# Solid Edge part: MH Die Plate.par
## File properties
Author: davee
Template: Normal.par
Last saved by: davee
Revision: 61
Application: Solid Edge
Accuracy: 0.990
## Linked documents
Loose Support Solid.par
LTS 300A SHAFT SUPPORT etd.par
LTS 300A SHAFT SUPPORT etd Solid.par
Loose Support.par
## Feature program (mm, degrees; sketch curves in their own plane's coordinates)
sketch for "unnamed Protrusion 1" plane through (0, 0, 0) normal (0, 0, 1) x-axis (1, 0, 0)
  line (-100, -100) -> (100, -100)
  line (100, -100) -> (100, 100)
  line (100, 100) -> (-100, 100)
  line (-100, 100) -> (-100, -100)
  dimension (linear) = 100
  dimension (linear) = 100
extrude "unnamed Protrusion 1" add finite 36.2 along -normal
sketch for "Hole_1" plane through (0, 0, 0) normal (0, 0, 1) x-axis (1, 0, 0)
hole "Hole_1" diameter 6 through
sketch for "Hole_2" plane through (0, 0, -36.2) normal (0, 0, -1) x-axis (-1, 0, 0)
  hole centre (-80, -49) bore radius 5.053
hole "Hole_2" finite  VBottomAngle = 118 deg; ThreadDepth = 2 mm
sketch for "unnamed Hole 1" plane through (0, 0, -36.2) normal (0, 0, -1) x-axis (-1, 0, 0)
  hole centre (80, -49) bore radius 5.053
hole "unnamed Hole 1" finite
sketch for "unnamed Hole 2" plane through (0, 0, -36.2) normal (0, 0, -1) x-axis (-1, 0, 0)
  hole centre (80, 49) bore radius 5.053
hole "unnamed Hole 2" finite
sketch for "unnamed Hole 3" plane through (0, 0, -36.2) normal (0, 0, -1) x-axis (-1, 0, 0)
  hole centre (-80, 49) bore radius 5.053
hole "unnamed Hole 3" finite
pattern "unnamed Pattern 1" of "Hole_2", "unnamed Hole 1", "unnamed Hole 2", "unnamed Hole 3"
sketch for "ExtrudedCutout_1" #1 plane through (0, 0, -36.2) normal (0, 0, -1) x-axis (-1, 0, 0)
  circle centre (77, 77) radius 16
sketch for "ExtrudedCutout_1" #2 plane through (0, 0, -36.2) normal (0, 0, -1) x-axis (-1, 0, 0)
  circle centre (77, -77) radius 16
sketch for "ExtrudedCutout_1" #3 plane through (0, 0, -36.2) normal (0, 0, -1) x-axis (-1, 0, 0)
  circle centre (-77, -77) radius 16
sketch for "ExtrudedCutout_1" #4 plane through (0, 0, -36.2) normal (0, 0, -1) x-axis (-1, 0, 0)
  circle centre (-77, 77) radius 16
extrude "ExtrudedCutout_1" cut finite 6 along -normal
sketch for "unnamed Cutout 1" #1 plane through (0, 0, -36.2) normal (0, 0, -1) x-axis (-1, 0, 0)
  circle centre (77, 77) radius 13.5
sketch for "unnamed Cutout 1" #2 plane through (0, 0, -36.2) normal (0, 0, -1) x-axis (-1, 0, 0)
  circle centre (77, -77) radius 13.5
sketch for "unnamed Cutout 1" #3 plane through (0, 0, -36.2) normal (0, 0, -1) x-axis (-1, 0, 0)
  circle centre (-77, -77) radius 13.5
sketch for "unnamed Cutout 1" #4 plane through (0, 0, -36.2) normal (0, 0, -1) x-axis (-1, 0, 0)
  circle centre (-77, 77) radius 13.5
extrude "unnamed Cutout 1" cut through along -normal
sketch for "Hole_6" plane through (0, 0, -36.2) normal (0, 0, -1) x-axis (-1, 0, 0)
hole "Hole_6" diameter 14 through  CounterBoreDepth = 5 mm; VBottomAngle = 118 deg
boolean "unnamed Boolean 1"
boolean "unnamed Boolean 2"
boolean "unnamed Boolean 3"
boolean "unnamed Boolean 4"
sketch for "Hole_18" plane through (0, 0, 0) normal (0, 0, 1) x-axis (0, -1, 0)
hole "Hole_18" diameter 3 through
sketch for "unnamed Hole 4" plane through (0, 0, 0) normal (0, 0, 1) x-axis (0, -1, 0)
hole "unnamed Hole 4" through
sketch for "unnamed Hole 5" plane through (0, 0, 0) normal (0, 0, 1) x-axis (0, -1, 0)
hole "unnamed Hole 5" through
sketch for "unnamed Hole 6" plane through (0, 0, 0) normal (0, 0, 1) x-axis (0, -1, 0)
  hole centre (-74, 13.1725) bore radius 1.5
  dimension (linear) = 74
hole "unnamed Hole 6" through
sketch for "Hole_23" plane through (0, 0, 0) normal (0, 0, 1) x-axis (1, 0, 0)
hole "Hole_23" diameter 6 through
sketch for "unnamed Hole 7" plane through (0, 0, 0) normal (0, 0, 1) x-axis (1, 0, 0)
hole "unnamed Hole 7" through
sketch for "Hole_25" plane through (0, 0, 0) normal (0, 0, 1) x-axis (1, 0, 0)
  hole centre (40, 85) bore radius 5
hole "Hole_25" diameter 10 through  VBottomAngle = 118 deg
sketch for "unnamed Hole 8" plane through (0, 0, 0) normal (0, 0, 1) x-axis (1, 0, 0)
hole "unnamed Hole 8" through
sketch for "unnamed Hole 9" plane through (0, 0, 0) normal (0, 0, 1) x-axis (1, 0, 0)
hole "unnamed Hole 9" through
sketch for "unnamed Hole 10" plane through (0, 0, 0) normal (0, 0, 1) x-axis (1, 0, 0)
hole "unnamed Hole 10" through
pattern "unnamed Pattern 2" of "Hole_18", "unnamed Hole 4", "unnamed Hole 5", "unnamed Hole 6"
pattern "unnamed Pattern 3" of "Hole_23", "unnamed Hole 7"
pattern "unnamed Pattern 4" of "Hole_25", "unnamed Hole 8", "unnamed Hole 9", "unnamed Hole 10"
Other named dimensions: "CoordinateSystem_1": Z_Rotation = 90 deg; X_Translation = 6.06 mm; Y_Translation = -30 mm; Z_Translation = -5.08 mm | "CopyConstruction_2": XScale = 1.01; YScale = 1.01; ZScale = 1.01 | "CopyConstruction_3": XScale = 1.01; YScale = 1.01; ZScale = 1.01 | "CoordinateSystem_2": X_Rotation = -90 deg; Y_Rotation = 180 deg; Z_Rotation = 180 deg; Y_Translation = 80 mm; Z_Translation = -8.12 mm | "CopyConstruction_4": XScale = 1.015; YScale = 1.015; ZScale = 1.015 | "CopyConstruction_5": XScale = 1.015; YScale = 1.015; ZScale = 1.015 | "ExtrudedSurface_4": FiniteDepth2 = 47.625 mm | "ExtrudedSurface_6": FiniteDepth = 69.85 mm; FiniteDepth2 = 34.925 mm
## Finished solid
Body 1: solid body, 3 faces, 2 edges, 0 vertices.
  Faces by surface: plane 2, cylinder 1
  Edges by curve: circle 2
Body 2: solid body, 3 faces, 2 edges, 0 vertices.
  Faces by surface: plane 2, cylinder 1
  Edges by curve: circle 2
Body 3: solid body, 3 faces, 2 edges, 0 vertices.
  Faces by surface: plane 2, cylinder 1
  Edges by curve: circle 2
Body 4: solid body, 89 faces, 205 edges, 116 vertices.
  Faces by surface: plane 43, cylinder 32, sphere 6, torus 4, blend 2, cone 2
  Edges by curve: line 136, circle 59, ellipse 10
Body 5: solid body, 58 faces, 126 edges, 70 vertices.
  Faces by surface: cylinder 25, plane 21, sphere 6, torus 4, blend 2
  Edges by curve: line 76, circle 40, ellipse 10
Body 6: solid body, 119 faces, 270 edges, 158 vertices.
  Faces by surface: plane 45, cylinder 24, torus 20, cone 14, spline 6, swept 6, spun 4
  Edges by curve: line 146, circle 80, curve on surface 18, spline 18, intersection 8
Body 7: solid body, 26 faces, 56 edges, 32 vertices.
  Faces by surface: cylinder 12, torus 8, plane 6
  Edges by curve: circle 32, line 24
Body 8: solid body, 236 faces, 512 edges, 273 vertices.
  Faces by surface: plane 103, cylinder 73, cone 20, torus 20, spline 6, swept 6, sphere 4, spun 4
  Edges by curve: line 288, circle 174, curve on surface 18, spline 18, intersection 8, ellipse 6
Bounding box of the edges (mm; curved faces can reach further): 200.000 x 247.625 x 104.775, from (-100, -100, -69.85) to (100, 147.625, 34.925).
Cylindrical faces by radius (mm): R0.7575 x12, R0.808 x12, R0.812 x6, R1.01 x22, R1.1165 x4, R1.5 x4, R1.515 x6, R1.6747 x4, R2.03 x52, R2.233 x4, R3 x3, R3.03 x8, R3.045 x6, R5 x6, R5.053 x4, R7 x1, R10 x1, R10.15 x2, R13.5 x4, R15 x1, R16 x4, R25.8825 x3
Conical faces (half-angle, radius in mm at the cone's reference point): 1 deg R1.7675 x4, 1 deg R2.424 x4, 3 deg R1.515 x16, 3 deg R3.8099 x2, 3 deg R3.8205 x2, 59 deg R2.233 x4, 59 deg R5.053 x4
Toroidal faces (ring radius, tube radius in mm): R0.505 r1.01 x6, R0.7575 r0.7575 x6, R2.02 r1.01 x6, R2.233 r0.812 x4, R2.2725 r0.7575 x6, R2.2818 r0.808 x16, R3.0431 r0.808 x2, R3.0538 r0.808 x2, R4.06 r2.03 x4, R5.43 r1.01 x2, R5.4406 r1.01 x2
Spherical faces by radius (mm): R2.03 x16
Planar faces by outward normal: +x 28, +y 29, +z 35, -x 28, -y 28, -z 38, oblique 38
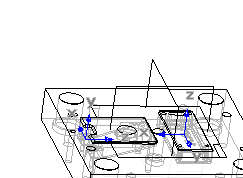
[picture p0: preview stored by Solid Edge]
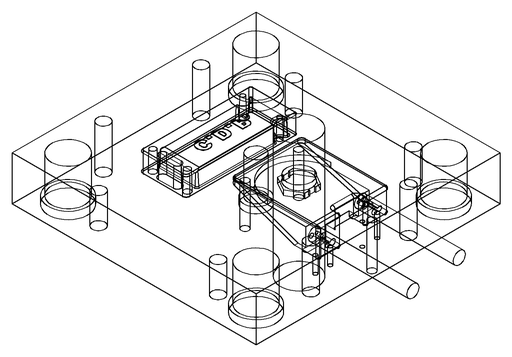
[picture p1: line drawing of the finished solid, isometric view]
